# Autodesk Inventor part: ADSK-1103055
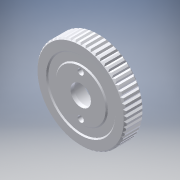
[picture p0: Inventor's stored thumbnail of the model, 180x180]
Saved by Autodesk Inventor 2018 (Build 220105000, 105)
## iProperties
Shininess: 50.0
Length Units: 11272
Angle Units: 11279
Time Units: 11290
Mass Units: 11286
Length Display Precision: 4
Angle Display Precision: 2
Compacted: True
Created: 2000-08
Part Number: ADSK-1103055
Document SubType Name: Modeling
Mass: 8.22663 g
Surface Area: 26.2406 cm^2
Volume: 3.03566 cm^3
Density: 2.71 g/cm^3
Material: Aluminum-6061
Appearance: Aluminum - Flat
Density: 0.0
Volumn: 0.0
Area: 0.0
PropertySet Name: Model Information
Control State: 0
Master: False
Checked Out: False
Author: Autodesk, Inc.
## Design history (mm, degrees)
node "Extrusion1" dims "d1" = 6.35, "d2" = 0
  sketch "Sketch3"
    geometry: C1 r 15.24 at (-0.476, 0)
    constraints: 1 centre point
    dimensions: "d0" = 30.48 diameter of C1
node "Chamfer1" dims "d3" = 0.508, "d4" = 0.508, "d48" = 45 deg
node "Extrusion2" dims "d6" = 6.35, "d7" = 0
  sketch "Sketch4"
    geometry: L1 (0, 14.732)-(-0.508, 15.24); L2 (-0.508, 15.24)-(0.508, 15.24); L3 (0.508, 15.24)-(0, 14.732); C1 r 15.24 at (0, 0) reference; 1 further point
    constraints: 6 end point, 2 vertical alignment, 1 horizontal, 1 perpendicular, 1 tangent, 1 other
    dimensions: "d5" = 90 deg angle of L3 L1
node "Extrusion3" dims "d12" = 6.35, "d13" = -15 deg
  sketch "Sketch5"
    geometry: C1 r 5.715 at (0.476, 0); A1 r 14.732 centre (0.476, 0) between (3.813, 14.349) and (2.155, 14.636) reference
    constraints: 1 centre point, 1 coincident
    dimensions: "d11" = 11.43 diameter of C1
node "Extrusion4" dims "d15" = 6.35, "d16" = 0
  sketch "Sketch6"
    geometry: C1 r 4.014 at (-0.476, 0) reference; C2 r 4.128 at (-0.476, 0); A1 r 14.732 centre (-0.476, 0) between (10.089, 10.267) and (8.85, 11.405) reference
    constraints: 1 centre point, 1 coincident
    dimensions: "d14" = 8.255 diameter of C2
node "Hole1" dims "d18" = 2.0955, "d19" = 9.525, "d20" = 6.35, "d21" = 60 deg, "d22" = 19.05, "d23" = 118 deg
  sketch "Sketch7"
    geometry: 4 further points
    constraints: 1 vertical alignment, 1 other
    dimensions: "d17" = 6.985 distance of point (-0.476, 0) point (-0.476, 6.985)
node "Circular Pattern2" dims "d24" = 20, "d26" = 360 deg
workplane "Work Plane1"
  workaxis "Work Axis1"
  workaxis "Work Axis2"
node "Extrusion5" dims "d28" = 3.175, "d29" = -10 deg
  sketch "Sketch8"
    geometry: C1 r 1.048 at (0.476, -6.985) reference; C2 r 1.048 at (-5.573, -3.493) reference; C3 r 1.048 at (0.476, 6.985) reference; C4 r 8.668 at (0.476, 0); C5 r 13.462 at (0.476, 0); A1 r 14.732 centre (0.476, 0) between (-2.861, 14.349) and (-4.475, 13.875) reference; A2 r 14.732 centre (0.476, 0) between (3.813, 14.349) and (2.155, 14.636) reference
    constraints: 2 centre point, 2 coincident
    dimensions: "d27" = 1.27 radial gap between concentric circles of A1 C5; "d34" = 17.3355 diameter of C4
node "Fillet3" dims "d35" = 0.8128
node "Chamfer2" dims "d36" = 0.127, "d37" = 0.127, "d49" = 45 deg
node "Extrusion6" dims "d40" = 1.27, "d41" = 0
  sketch "Sketch9"
    geometry: C1 r 4.763 at (-0.476, 0); C2 r 3.493 at (-0.476, 0); A1 r 14.732 centre (-0.476, 0) between (2.861, 14.349) and (1.204, 14.636) reference
    constraints: 2 centre point, 2 coincident
    dimensions: "d38" = 6.985 diameter of C2; "d39" = 1.27 radial gap between concentric circles of C1 C2
node "Extrusion7" dims "d44" = 0.381, "d45" = 0
  sketch "Sketch10"
    geometry: C1 r 8.89 at (-0.476, 0); C2 r 11.43 at (-0.476, 0); C3 r 4.354 at (-0.476, 0) reference; A1 r 14.732 centre (-0.476, 0) between (5.259, -13.57) and (6.768, -12.828) reference
    constraints: 2 centre point, 2 concentric
    dimensions: "d42" = 17.78 diameter of C1; "d43" = 22.86 diameter of C2
node "Chamfer3" dims "d46" = 0.381, "d47" = 0.381, "d50" = 45 deg
body "Solid1"
node "Circular Pattern1" dims "d8" = 550, "d10" = 360 deg
